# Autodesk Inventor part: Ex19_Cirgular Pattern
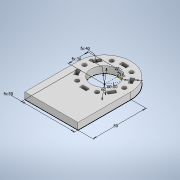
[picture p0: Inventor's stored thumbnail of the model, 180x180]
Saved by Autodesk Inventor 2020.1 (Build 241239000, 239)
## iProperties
Created: 2019-11
Part Number: Ex19_Cirgular Pattern
Material: Generic
Document SubType Name: Modeling
Designer: Synergysoft Dell02
Density: 1 g/cm^3
Appearance: Default
Author: Synergysoft Dell02
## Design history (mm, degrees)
sketch "Sketch1"
  geometry: L1 (-40, 40)-(40, 40); L2 (40, 40)-(40, -40); L3 (40, -40)-(-40, -40); L4 (-40, -40)-(-40, 40); L5 (-40, 40)-(40, -40); L6 (40, 40)-(-40, -40); C1 r 20 at (0, -40); A1 r 40 centre (0, -40) between (-40, -40) and (40, -40); 1 further point
  constraints: 12 end point, 2 centre point, 2 midpoint, 2 parallel, 2 point on circle, 1 coincident, 1 horizontal, 1 perpendicular
  dimensions: "d2" = 80 distance of L2.end L3.end (= d3); "d3" = 80 distance between parallel lines of L1 L3; "d24" = 40 radius of A1 (= 0.5 x d3); "d25" = 40 diameter of C1
extrude "Extrusion1" new body sketch "Sketch1" distance "d6" = 10; taper "d7" = 0 deg
sketch "Sketch2"
  geometry: L1 (5, -72.5)-(-5, -72.5); L2 (-5, -72.5)-(-5, -67.5); L3 (-5, -67.5)-(5, -67.5); L4 (5, -67.5)-(5, -72.5); L5 (5, -72.5)-(-5, -67.5); L6 (-5, -72.5)-(5, -67.5); C1 r 20 at (0, -40) reference; 3 further points
  constraints: 12 end point, 3 midpoint, 2 parallel, 1 horizontal, 1 perpendicular, 1 vertical alignment
  dimensions: "d8" = 10 distance of L2.end L3.end; "d9" = 5 distance of L1.end L2.end; "d10" = 30 distance of C1.centre point (0, -70) (computed from d25)
extrude "Extrusion2" cut sketch "Sketch2" extent not by distance; stored distance "d11" = 0; taper "d12" = 0 deg
pattern_circular "Circular Pattern1" dims angle "d14" = 360 deg
sketch "Sketch3" dims "d17" = 60
  geometry: L1 (0, -40)-(0, -68); L2 (0, -40)-(33, -40); L3 (0, -40)-(15, -65.981); C1 r 3 at (15, -65.981); C2 r 20 at (0, -40) reference; 1 further point
  constraints: 6 end point, 1 centre point, 1 coincident, 1 horizontal, 1 vertical, 3 other
  dimensions: "d16" = 6 diameter of C1; "d18" = 60 deg angle of L2 L3
extrude "Extrusion3" cut sketch "Sketch3" distance "d19" = 10; taper "d20" = 0 deg
pattern_circular "Circular Pattern2" dims angle "d22" = 360 deg
body "Solid1"
